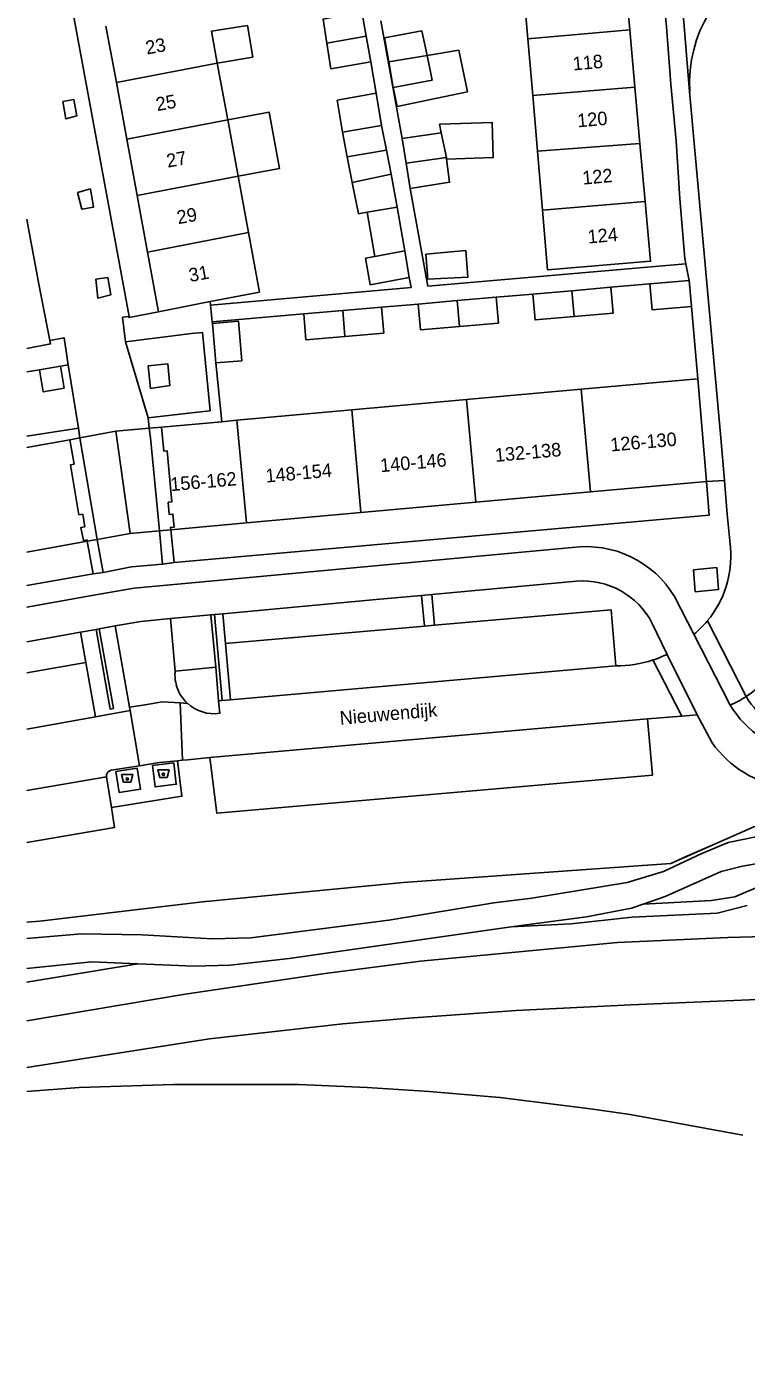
# Model space of a CAD drawing. Extents: x 194485 to 197793, y 468269 to 470822.
# Drawn here: x 194485.4 to 194549.1, y 469167.8 to 469286.4 of the extents above; entities that cross this region are included whole.
import ezdxf

# ---------------------------------------------------------------- set-up
doc = ezdxf.new("R2010")
doc.units = 0
for name, color, linetype in [('BGT begrenzing pand op maaiveld onder overbouw', 7, 'Continuous'), ('BGT grensvlak begroeid terreindeel', 7, 'Continuous'), ('BGT grensvlak gebouwinstallatie plus 1', 7, 'Continuous'), ('BGT grensvlak onbegroeid terreindeel', 7, 'Continuous'), ('BGT grensvlak onbegroeid terreindeel LR', 7, 'Continuous'), ('BGT grensvlak pand deel overbouw', 7, 'Continuous'), ('BGT grensvlak pand op maaiveld', 7, 'Continuous'), ('BGT grensvlak pand op maaiveld LR', 7, 'Continuous'), ('BGT grensvlak scheiding', 7, 'Continuous'), ('BGT grensvlak wegdeel', 7, 'Continuous'), ('BGT lijnelement scheiding hek', 7, 'Continuous'), ('BGT lijnelement spoor trein', 7, 'Continuous'), ('BGT puntobject bak afval apart plaats', 7, 'Continuous'), ('BGT tekst huisnummerreeks', 7, 'Continuous'), ('BGT tekst openbare ruimte label weg', 7, 'Continuous')]:
    doc.layers.add(name, color=color, linetype=linetype)

msp = doc.modelspace()

# ---------------------------------------------------------------- linework, layer by layer
at = {"layer": 'BGT begrenzing pand op maaiveld onder overbouw'}
for p, q in [((194489.22, 469249.84), (194489.6, 469247.66)), ((194490.36, 469243.26), (194490.55, 469242.13)), ((194490.75, 469240.96), (194490.77, 469240.85))]:
    msp.add_line(p, q, dxfattribs=at)
for points in [[(194497.34, 469250.95), (194497.53, 469248.83), (194497.85, 469248.85), (194498.25, 469244.33), (194497.93, 469244.3), (194498.03, 469243.23), (194498.35, 469243.26), (194498.45, 469242.1), (194498.13, 469242.07), (194498.15, 469241.87)], [(194490.36, 469243.26), (194490.03, 469243.2), (194489.28, 469247.61), (194489.6, 469247.66)], [(194490.75, 469240.96), (194490.43, 469240.9), (194490.2, 469242.07), (194490.55, 469242.13)]]:
    msp.add_lwpolyline(points, dxfattribs=at)
at = {"layer": 'BGT grensvlak begroeid terreindeel'}
msp.add_lwpolyline([(194552.88, 469216), (194551.49, 469215.85), (194549.79, 469215.55), (194546.51, 469214.1), (194543.86, 469212.94), (194542.44, 469212.31), (194518.73, 469210.61), (194500.96, 469208.9), (194486.58, 469207.21), (194485.41, 469207.11)], dxfattribs=at)
at = {"layer": 'BGT grensvlak gebouwinstallatie plus 1'}
for p, q in [((194504.95, 469286.53), (194505.42, 469283.73)), ((194520.85, 469283.87), (194523.65, 469284.34)), ((194523.65, 469284.34), (194524.42, 469280.64)), ((194505.42, 469283.73), (194502.28, 469283.19)), ((194518.2, 469279.34), (194517.85, 469281.03)), ((194524.42, 469280.64), (194518.2, 469279.34)), ((194516.35, 469280.52), (194512.89, 469279.91)), ((194512.89, 469279.91), (194513.35, 469277.09)), ((194516.35, 469280.52), (194516.83, 469277.67)), ((194514.78, 469269.85), (194514.21, 469272.61)), ((194517.66, 469273.36), (194518.19, 469270.43)), ((194514.92, 469269.87), (194514.78, 469269.85)), ((194515.54, 469269.98), (194514.92, 469269.87)), ((194518.19, 469270.43), (194515.54, 469269.98)), ((194516.22, 469266.07), (194515.54, 469269.98)), ((194518.19, 469270.43), (194518.89, 469266.56))]:
    msp.add_line(p, q, dxfattribs=at)
for points in [[(194503.2, 469278.18), (194506.86, 469278.86), (194507.78, 469273.86), (194504.12, 469273.18)], [(194522.58, 469274.68), (194526.71, 469274.83), (194526.61, 469277.94), (194521.96, 469277.78), (194522.11, 469277.01)]]:
    msp.add_lwpolyline(points, dxfattribs=at)
at = {"layer": 'BGT grensvlak onbegroeid terreindeel'}
for points in [[(194485.41, 469205.66), (194490.26, 469206.08), (194495.63, 469205.99), (194501.82, 469205.62), (194505.24, 469205.72), (194517.47, 469207.28), (194526.76, 469208.83), (194530.12, 469209.24), (194538.57, 469210.63), (194541.79, 469211.59), (194545.18, 469213.19), (194547.52, 469214.17), (194551.54, 469214.98), (194553.41, 469215.44), (194554.24, 469216.02)], [(194539.99, 469208.71), (194541.92, 469209.38), (194546.88, 469211.6), (194548.78, 469212.08), (194554.02, 469212.98), (194555.43, 469213.6), (194556.11, 469214.6), (194556.85, 469215.93)], [(194539.99, 469208.71), (194546.04, 469209.04), (194548.1, 469209.36), (194550.51, 469210.39), (194554.35, 469211.64), (194558.24, 469212.77), (194562.55, 469213.18), (194568.75, 469213.35), (194575.33, 469213.82), (194579.87, 469213.68), (194580.81, 469213.49), (194581.53, 469212.99), (194583.52, 469210.83), (194585.95, 469209.01), (194591.07, 469208.48), (194601.74, 469207.83), (194603.36, 469207.9), (194605.46, 469208.76), (194607.78, 469209.17)], [(194495.25, 469203.42), (194491.18, 469203.59), (194485.41, 469203)]]:
    msp.add_lwpolyline(points, dxfattribs=at)
at = {"layer": 'BGT grensvlak onbegroeid terreindeel LR'}
for points in [[(194539.99, 469208.71), (194538.94, 469208.35), (194534.98, 469207.59)], [(194528.29, 469206.69), (194530.06, 469206.94), (194534.98, 469207.59)]]:
    msp.add_lwpolyline(points, dxfattribs=at)
at = {"layer": 'BGT grensvlak pand deel overbouw'}
for p, q in [((194497.34, 469250.95), (194496.26, 469250.85)), ((194489.22, 469249.84), (194490.12, 469250.01)), ((194490.12, 469250.01), (194493.28, 469250.59)), ((194496.26, 469250.85), (194493.28, 469250.59)), ((194493.28, 469250.59), (194494.57, 469241.54)), ((194494.57, 469241.54), (194491.65, 469241.01)), ((194497.16, 469241.78), (194494.57, 469241.54)), ((194498.15, 469241.87), (194497.16, 469241.78)), ((194491.65, 469241.01), (194490.77, 469240.85))]:
    msp.add_line(p, q, dxfattribs=at)
at = {"layer": 'BGT grensvlak pand op maaiveld'}
for p, q in [((194538.8, 469286.14), (194538.35, 469291.24)), ((194529.34, 469290.32), (194529.77, 469285.35)), ((194515.47, 469285.58), (194515.08, 469287.76)), ((194493.34, 469281.47), (194492.42, 469286.48)), ((194515.47, 469285.58), (194515.87, 469283.31)), ((194530.2, 469280.33), (194529.77, 469285.35)), ((194539.26, 469281.08), (194538.8, 469286.14)), ((194503.2, 469278.18), (194502.28, 469283.19)), ((194517.85, 469281.03), (194517.46, 469283.31)), ((194494.27, 469276.46), (194493.34, 469281.47)), ((194539.7, 469276.07), (194539.26, 469281.08)), ((194530.2, 469280.33), (194530.62, 469275.4)), ((194504.12, 469273.18), (194503.2, 469278.18)), ((194516.83, 469277.67), (194513.35, 469277.09)), ((194513.35, 469277.09), (194513.78, 469274.89)), ((194517.25, 469275.5), (194516.83, 469277.67)), ((194522.11, 469277.01), (194518.64, 469276.52)), ((194522.56, 469274.85), (194522.11, 469277.01)), ((194495.19, 469271.46), (194494.27, 469276.46)), ((194518.64, 469276.52), (194519, 469274.33)), ((194539.7, 469276.07), (194540.16, 469270.93)), ((194514.21, 469272.61), (194513.78, 469274.89)), ((194517.25, 469275.5), (194517.66, 469273.36)), ((194522.56, 469274.85), (194522.58, 469274.68)), ((194530.62, 469275.4), (194531.06, 469270.17)), ((194519.36, 469272.1), (194519, 469274.33)), ((194504.12, 469273.18), (194505.04, 469268.18)), ((194517.66, 469273.36), (194514.21, 469272.61)), ((194496.11, 469266.45), (194495.19, 469271.46)), ((194497.08, 469261.17), (194496.11, 469266.45)), ((194518.89, 469266.56), (194516.22, 469266.07)), ((194519.27, 469264.22), (194518.89, 469266.56)), ((194540.58, 469263.64), (194544.07, 469263.95)), ((194544.07, 469263.95), (194544.26, 469261.65)), ((194533.68, 469263.04), (194530.22, 469262.74)), ((194537.13, 469263.34), (194533.68, 469263.04)), ((194501.65, 469262.07), (194497.08, 469261.17)), ((194516.83, 469261.58), (194513.38, 469261.28)), ((194523.52, 469262.16), (194520.07, 469261.86)), ((194526.97, 469262.46), (194523.52, 469262.16)), ((194513.38, 469261.28), (194509.93, 469260.98)), ((194502.14, 469256.64), (194501.84, 469260.14)), ((194544.81, 469255.24), (194534.5, 469254.31)), ((194545.59, 469246.13), (194544.81, 469255.24)), ((194524.34, 469253.39), (194514.18, 469252.48)), ((194534.5, 469254.31), (194524.34, 469253.39)), ((194514.18, 469252.48), (194504.02, 469251.56)), ((194502.67, 469251.43), (194497.34, 469250.95)), ((194504.02, 469251.56), (194502.67, 469251.43)), ((194485.41, 469249.14), (194489.22, 469249.84)), ((194535.32, 469245.21), (194545.59, 469246.13)), ((194525.16, 469244.3), (194535.32, 469245.21)), ((194515, 469243.38), (194525.16, 469244.3)), ((194504.85, 469242.47), (194515, 469243.38)), ((194504.85, 469242.47), (194498.15, 469241.87)), ((194490.77, 469240.85), (194485.41, 469239.87))]:
    msp.add_line(p, q, dxfattribs=at)
for points in [[(194515.08, 469287.76), (194511.64, 469287.08), (194511.98, 469284.95)], [(194502.28, 469283.19), (194501.76, 469286.02), (194504.95, 469286.53)], [(194520.85, 469283.87), (194520.39, 469286.05), (194517.09, 469285.44), (194517.46, 469283.31)], [(194515.87, 469283.31), (194512.33, 469282.7), (194511.98, 469284.95)], [(194520.85, 469283.87), (194521.3, 469281.68), (194517.85, 469281.03)], [(194522.58, 469274.68), (194522.85, 469272.65), (194519.36, 469272.1)], [(194540.16, 469270.93), (194540.64, 469265.64), (194531.51, 469264.9), (194531.06, 469270.17)], [(194505.04, 469268.18), (194506.01, 469262.91), (194501.65, 469262.07)], [(194520.74, 469266.26), (194520.89, 469264.41), (194520.9, 469264.05), (194524.45, 469264.23), (194524.27, 469266.59), (194520.74, 469266.26)], [(194516.22, 469266.07), (194515.4, 469265.92), (194515.82, 469263.56), (194519.27, 469264.22)], [(194530.22, 469262.74), (194530.42, 469260.45), (194533.88, 469260.75)], [(194533.88, 469260.75), (194537.33, 469261.05), (194537.13, 469263.34)], [(194544.26, 469261.65), (194540.77, 469261.35), (194540.58, 469263.64)], [(194513.58, 469258.99), (194517.02, 469259.29), (194516.83, 469261.58)], [(194520.07, 469261.86), (194520.27, 469259.57), (194523.72, 469259.87)], [(194523.72, 469259.87), (194527.17, 469260.17), (194526.97, 469262.46)], [(194509.93, 469260.98), (194510.13, 469258.69), (194513.58, 469258.99)], [(194501.84, 469260.14), (194504.15, 469260.34), (194504.45, 469256.84), (194502.14, 469256.64)]]:
    msp.add_lwpolyline(points, dxfattribs=at)
at = {"layer": 'BGT grensvlak pand op maaiveld LR'}
for p, q in [((194511.98, 469284.95), (194515.47, 469285.58)), ((194529.77, 469285.35), (194538.8, 469286.14)), ((194493.34, 469281.47), (194502.28, 469283.19)), ((194517.46, 469283.31), (194520.85, 469283.87)), ((194530.2, 469280.33), (194539.26, 469281.08)), ((194494.27, 469276.46), (194503.2, 469278.18)), ((194530.62, 469275.4), (194539.7, 469276.07)), ((194513.78, 469274.89), (194517.25, 469275.5)), ((194519, 469274.33), (194522.56, 469274.85)), ((194495.19, 469271.46), (194504.12, 469273.18)), ((194531.06, 469270.17), (194540.16, 469270.93)), ((194496.11, 469266.45), (194505.04, 469268.18)), ((194533.68, 469263.04), (194533.88, 469260.75)), ((194523.52, 469262.16), (194523.72, 469259.87)), ((194513.38, 469261.28), (194513.58, 469258.99)), ((194525.16, 469244.3), (194524.34, 469253.39)), ((194535.32, 469245.21), (194534.5, 469254.31)), ((194515, 469243.38), (194514.18, 469252.48)), ((194504.85, 469242.47), (194504.02, 469251.56))]:
    msp.add_line(p, q, dxfattribs=at)
at = {"layer": 'BGT grensvlak scheiding'}
for p, q in [((194501.72, 469234.32), (194502.02, 469234.35)), ((194501.72, 469234.32), (194502.15, 469229.69)), ((194502.02, 469234.35), (194502.72, 469226.75)), ((194491.54, 469233.04), (194491.83, 469233.09)), ((194491.83, 469233.09), (194493.09, 469226.02)), ((194491.54, 469233.04), (194492.8, 469225.97)), ((194502.15, 469229.69), (194502.39, 469226.72)), ((194492.8, 469225.97), (194493.09, 469226.02)), ((194502.72, 469226.75), (194502.39, 469226.72))]:
    msp.add_line(p, q, dxfattribs=at)
at = {"layer": 'BGT grensvlak wegdeel'}
for p, q in [((194494.46, 469260.74), (194487.7, 469297.53)), ((194544.1, 469280.67), (194543.4, 469289.02)), ((194516.77, 469286.95), (194518.64, 469276.52)), ((194515.87, 469283.31), (194516.35, 469280.52)), ((194544.07, 469263.95), (194543.77, 469265.43)), ((194526.97, 469262.46), (194530.22, 469262.74)), ((194537.13, 469263.34), (194540.58, 469263.64)), ((194501.68, 469261.77), (194501.65, 469262.07)), ((194501.83, 469260.28), (194501.68, 469261.77)), ((194516.83, 469261.58), (194520.07, 469261.86)), ((194544.26, 469261.65), (194544.81, 469255.24)), ((194501.83, 469260.28), (194509.93, 469260.98)), ((194501.84, 469260.14), (194501.83, 469260.28)), ((194494.14, 469258.51), (194496.16, 469251.78)), ((194485.41, 469255.85), (194486.54, 469256.04)), ((194488.39, 469256.35), (194486.54, 469256.04)), ((194488.39, 469256.35), (194489.08, 469256.47)), ((194489.08, 469256.47), (194489.98, 469250.87)), ((194502.14, 469256.64), (194502.67, 469251.43)), ((194489.98, 469250.87), (194485.41, 469250.16)), ((194490.12, 469250.01), (194489.98, 469250.87)), ((194496.26, 469250.85), (194496.16, 469251.78)), ((194491.65, 469241.01), (194490.12, 469250.01)), ((194545.59, 469246.13), (194547.17, 469246.24)), ((194497.16, 469241.78), (194497.44, 469238.83)), ((194498.46, 469238.95), (194498.15, 469241.87)), ((194491.29, 469237.96), (194490.77, 469240.85)), ((194492.17, 469238.09), (194491.65, 469241.01)), ((194491.29, 469237.96), (194485.41, 469236.92)), ((194492.17, 469238.09), (194491.29, 469237.96)), ((194497.44, 469238.83), (194498.46, 469238.95)), ((194521.27, 469236.13), (194534.09, 469237.32)), ((194520.37, 469236.05), (194521.27, 469236.13)), ((194520.62, 469233.32), (194520.37, 469236.05)), ((194521.27, 469236.13), (194521.5, 469233.4)), ((194542.76, 469235.95), (194544.48, 469232.61)), ((194498.12, 469233.99), (194501.72, 469234.32)), ((194502.02, 469234.35), (194502.76, 469234.42)), ((194502.76, 469234.42), (194502.99, 469231.78)), ((194491.83, 469233.09), (194493.23, 469233.34)), ((194494.51, 469226.14), (194493.23, 469233.34)), ((194498.54, 469229.34), (194498.12, 469233.99)), ((194502.99, 469231.78), (194520.62, 469233.32)), ((194520.62, 469233.32), (194521.5, 469233.4)), ((194540.79, 469233.57), (194542.11, 469230.83)), ((194545.67, 469233.79), (194549.11, 469227.09)), ((194485.41, 469231.95), (194490.18, 469232.8)), ((194490.18, 469232.8), (194491.54, 469233.04)), ((194490.18, 469232.8), (194490.64, 469230.11)), ((194544.48, 469232.61), (194547.7, 469226.34)), ((194502.99, 469231.78), (194503.44, 469226.81)), ((194542.11, 469230.83), (194544.76, 469225.47)), ((194485.41, 469229.18), (194490.64, 469230.11)), ((194490.64, 469230.11), (194491.48, 469225.3)), ((194498.54, 469229.34), (194502.15, 469229.69)), ((194537.56, 469229.81), (194503.44, 469226.81)), ((194540.85, 469230.33), (194543.41, 469225.36)), ((194494.56, 469225.86), (194494.51, 469226.14)), ((194499.21, 469221.45), (194499, 469226.54)), ((194499, 469226.54), (194499.63, 469226.49)), ((194502.39, 469226.72), (194502.49, 469225.6)), ((194503.44, 469226.81), (194502.72, 469226.75)), ((194491.48, 469225.3), (194485.41, 469224.21)), ((194491.48, 469225.3), (194494.56, 469225.86)), ((194494.56, 469225.86), (194495.39, 469220.96)), ((194501.62, 469221.69), (194540.36, 469225.12)), ((194543.41, 469225.36), (194540.36, 469225.12)), ((194544.76, 469225.47), (194543.41, 469225.36)), ((194546.09, 469222.99), (194544.76, 469225.47)), ((194499.21, 469221.45), (194498.75, 469221.41)), ((194499.66, 469221.5), (194499.21, 469221.45)), ((194501.62, 469221.69), (194499.66, 469221.5)), ((194495.39, 469220.96), (194492.88, 469220.56)), ((194492.47, 469219.99), (194485.41, 469218.78)), ((194492.47, 469219.99), (194492.91, 469217.26)), ((194485.41, 469201.78), (194495.25, 469203.42)), ((194495.25, 469203.42), (194498.83, 469203.26))]:
    msp.add_line(p, q, dxfattribs=at)
for points in [[(194543.77, 469265.43), (194543.68, 469265.89), (194543.24, 469271.19), (194542.9, 469276.32), (194542.42, 469281.34), (194542.04, 469286.42), (194541.54, 469291.52), (194540.77, 469299.03), (194536.02, 469304.73), (194532.61, 469308.59), (194529.45, 469312.58), (194526.12, 469316.47), (194522.88, 469320.24), (194520.35, 469323.36)], [(194544.1, 469280.67), (194546.85, 469250), (194547.17, 469246.24)], [(194488.59, 469279.8), (194489.57, 469279.97), (194489.83, 469278.52), (194488.88, 469278.26), (194488.59, 469279.8)], [(194489.89, 469271.75), (194491.04, 469272.05), (194491.32, 469270.45), (194490.29, 469270.26), (194489.89, 469271.75)], [(194543.77, 469265.43), (194520.92, 469263.45), (194519.36, 469272.1)], [(194485.41, 469269.36), (194485.55, 469268.54), (194486.47, 469263.63), (194487.46, 469258.63)], [(194491.51, 469264.07), (194492.58, 469264.22), (194492.85, 469262.67), (194491.7, 469262.38), (194491.51, 469264.07)], [(194501.68, 469261.77), (194519.43, 469263.32), (194519.27, 469264.22)], [(194494.14, 469258.51), (194493.89, 469260.68), (194494.46, 469260.74)], [(194497.08, 469261.17), (194494.47, 469260.66), (194494.46, 469260.74)], [(194496.16, 469251.78), (194500, 469252.22), (194501.65, 469252.4), (194500.96, 469259.35), (194500, 469259.24), (194494.14, 469258.51)], [(194487.46, 469258.63), (194487.52, 469258.32), (194485.41, 469257.92)], [(194489.08, 469256.47), (194488.71, 469258.87), (194487.46, 469258.63)], [(194486.54, 469256.04), (194486.87, 469254.07), (194488.71, 469254.42), (194488.39, 469256.35)], [(194496.15, 469256.38), (194497.89, 469256.57), (194498.07, 469254.63), (194496.37, 469254.39), (194496.15, 469256.38)], [(194496.26, 469250.85), (194496.36, 469250), (194497.16, 469241.78)], [(194545.59, 469246.13), (194545.84, 469243.17), (194498.46, 469238.95)], [(194547.71, 469240.29), (194547.43, 469243.25), (194547.17, 469246.24)], [(194533.71, 469240.29), (194500.36, 469237.19), (194494.93, 469236.69), (194492.53, 469236.27), (194490.84, 469235.97), (194485.41, 469235)], [(194492.17, 469238.09), (194494.68, 469238.57), (194497.44, 469238.83)], [(194544.44, 469238.32), (194544.59, 469236.38), (194546.66, 469236.58), (194546.5, 469238.52), (194544.44, 469238.32)], [(194502.76, 469234.42), (194516.34, 469235.68), (194520.37, 469236.05)], [(194521.5, 469233.4), (194537.16, 469234.77), (194537.56, 469229.81)], [(194493.23, 469233.34), (194493.24, 469233.34), (194495.52, 469233.75), (194498.12, 469233.99)], [(194499, 469226.54), (194497.4, 469226.62), (194495.88, 469226.37), (194494.51, 469226.14)], [(194540.36, 469225.12), (194540.82, 469220.14), (194502.23, 469216.75), (194501.62, 469221.69)], [(194498.75, 469221.41), (194499.15, 469218.26), (194492.91, 469217.26)], [(194498.75, 469221.41), (194497.17, 469221.25), (194495.39, 469220.96)], [(194493.3, 469220.46), (194495.17, 469220.76), (194495.47, 469218.88), (194493.6, 469218.58), (194493.3, 469220.46)], [(194496.53, 469220.98), (194498.42, 469221.21), (194498.65, 469219.33), (194496.77, 469219.09), (194496.53, 469220.98)], [(194492.91, 469217.26), (194493.19, 469215.5), (194485.41, 469214.16)], [(194549.2, 469208.58), (194546.54, 469207.91), (194539.01, 469207.56), (194533.62, 469206.97), (194528.29, 469206.69)], [(194498.83, 469203.26), (194500.14, 469203.2), (194503.41, 469203.3), (194508.65, 469203.89), (194528.29, 469206.69)]]:
    msp.add_lwpolyline(points, dxfattribs=at)
for centre, radius, start, end in [((194556.16, 469281.39), 12.08, 113.1835, 183.4254), ((194534.95, 469231.27), 9.1, 30.9199, 97.8191), ((194538.81, 469239.51), 8.93, 320.1261, 4.9924), ((194534.62, 469230.41), 6.93, 27.1384, 94.39), ((194544.08, 469234.8), 9.2, 303.1363, 358.5763), ((194538.78, 469239.55), 8.98, 309.3757, 320.0931), ((194537.55, 469240.46), 10.65, 288.0464, 295.3039), ((194537.57, 469240.42), 10.61, 269.9499, 288.0311), ((194501.73, 469229.04), 3.2, 174.633, 180.3094), ((194502.05, 469229.03), 3.52, 180.0944, 195.3698), ((194502, 469229.03), 3.48, 195.619, 226.9977), ((194501.99, 469229.04), 3.47, 227.1783, 278.2505), ((194544.05, 469234.84), 9.25, 293.1874, 303.1135), ((194555.26, 469230.84), 8.81, 210.7629, 263.3359), ((194555.41, 469230.9), 7.37, 211.1471, 261.0022), ((194554.01, 469228.68), 9.76, 215.7176, 261.4397), ((194492.96, 469220.07), 0.5, 99.1663, 189.0414)]:
    msp.add_arc(centre, radius, start, end, dxfattribs=at)
at = {"layer": 'BGT lijnelement scheiding hek'}
msp.add_lwpolyline([(194485.41, 469207.11), (194486.58, 469207.21), (194500.96, 469208.9), (194518.73, 469210.61), (194542.44, 469212.31), (194549.79, 469215.55), (194551.49, 469215.85), (194553.38, 469216.05), (194558.98, 469215.83), (194569.69, 469215.65), (194571.96, 469215.77), (194587.39, 469215.48), (194591.01, 469210.14), (194616.05, 469208.69)], dxfattribs=at)
at = {"layer": 'BGT lijnelement spoor trein'}
for points in [[(194485.41, 469198.38), (194499.42, 469200.72), (194511.84, 469202.55), (194520.26, 469203.65), (194537.7, 469205.3), (194547.47, 469205.74), (194558.43, 469206.05), (194574.78, 469206.08), (194581.84, 469205.88), (194638.55, 469201.76), (194670.19, 469199.37), (194687.12, 469198.19), (194712.15, 469196.69), (194845.22, 469189.82), (194903.37, 469186.64), (195079.3, 469177.53), (195154.77, 469173.52), (195161.67, 469173.09), (195179.76, 469171.58), (195199.85, 469169.49), (195213.65, 469167.78)], [(194485.41, 469194.24), (194501.6, 469196.78), (194513.4, 469198.09), (194519.25, 469198.61), (194528.74, 469199.28), (194538.89, 469199.8), (194549.41, 469200.22), (194557.27, 469200.43), (194564.38, 469200.38), (194573.41, 469200.08), (194588.07, 469199.3), (194605.71, 469198.53), (194610.53, 469198.22)], [(194485.41, 469192.1), (194490.04, 469192.46), (194498.43, 469192.73), (194509.51, 469192.72), (194515.55, 469192.45), (194521.04, 469192.1), (194527.3, 469191.57), (194535.32, 469190.58), (194538.82, 469190.08), (194548.8, 469188.25)]]:
    msp.add_lwpolyline(points, dxfattribs=at)
at = {"layer": 'BGT puntobject bak afval apart plaats'}
for points in [[(194494.63, 469219.52), (194494.81, 469220.19), (194493.81, 469220.19), (194493.98, 469219.52)], [(194497.83, 469219.93), (194498.01, 469220.61), (194497.01, 469220.61), (194497.18, 469219.93)]]:
    msp.add_lwpolyline(points, close=True, dxfattribs=at)
for centre in [(194497.51, 469220.21), (194494.31, 469219.79)]:
    msp.add_circle(centre, 0.1, dxfattribs=at)
for centre, start, end in [((194497.51, 469220.21), 0, 180), ((194497.51, 469220.21), 180, 0), ((194494.31, 469219.79), 0, 180), ((194494.31, 469219.79), 180, 0)]:
    msp.add_arc(centre, 0.1, start, end, dxfattribs=at)

# ---------------------------------------------------------------- texts
at = {"layer": 'BGT tekst huisnummerreeks'}
for s, rotation, p in [('23', 10.4, (194496.04, 469283.95)), ('118', 5.1, (194533.8, 469282.54)), ('25', 10.4, (194496.96, 469278.94)), ('120', 5.1, (194534.2, 469277.5)), ('27', 10.4, (194497.89, 469273.93)), ('122', 5.1, (194534.65, 469272.43)), ('29', 10.4, (194498.81, 469268.92)), ('124', 5.1, (194535.12, 469267.21)), ('31', 10.4, (194499.87, 469263.8)), ('126-130', 5.1, (194537.13, 469248.79)), ('140-146', 5.1, (194516.75, 469246.96)), ('132-138', 5.1, (194526.91, 469247.87)), ('148-154', 5.1, (194506.6, 469246.04)), ('156-162', 5.1, (194498.17, 469245.28))]:
    msp.add_text(s, height=1.2, rotation=rotation, dxfattribs=at).set_placement(p)
at = {"layer": 'BGT tekst openbare ruimte label weg'}
msp.add_text('Nieuwendijk', height=1.2, rotation=5, dxfattribs=at).set_placement((194513.17, 469224.59))

doc.saveas('drawing.dxf')
